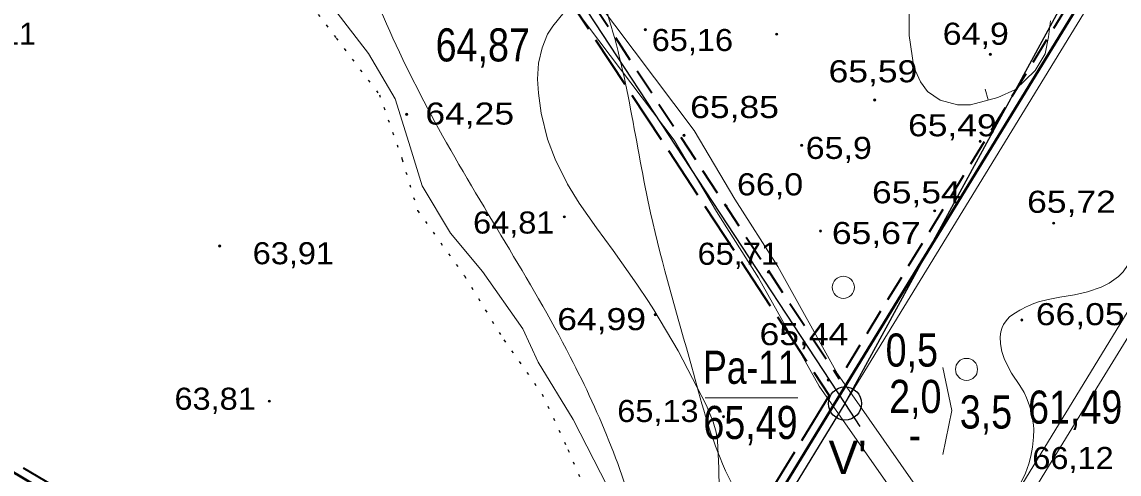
# Model space of a CAD drawing. Extents: x 628176 to 629009, y 6439913 to 6440496.
# Drawn here: x 628423 to 628522.3, y 6440112.2 to 6440153.1 of the extents above; entities that cross this region are included whole.
import ezdxf
from ezdxf.enums import TextEntityAlignment as Align

# ---------------------------------------------------------------- set-up
doc = ezdxf.new("R2010")
doc.units = 0
doc.header["$LTSCALE"] = 0.8
for name, pattern in [('DOTTED', [1.5, 0.3, -1.2]), ('LONG_DASHED', [7.5, 6, -1.5]), ('MEDIUM_DASHED', [4.5, 3, -1.5])]:
    doc.linetypes.add(name, pattern=pattern)
for name, color, linetype, lineweight in [('1', 7, 'Continuous', 13), ('11', 7, 'Continuous', 13), ('12', 7, 'Continuous', 13), ('14', 7, 'Continuous', 25), ('16', 7, 'Continuous', 13), ('21', 7, 'MEDIUM_DASHED', 35), ('3', 7, 'Continuous', 13), ('6', 7, 'Continuous', 13)]:
    doc.layers.add(name, color=color, linetype=linetype, lineweight=lineweight)

msp = doc.modelspace()

# ---------------------------------------------------------------- hatches: boundary and pattern name
at = {"layer": '1'}
for points in [[(628479.5318, 6440152.407, 1), (628479.3318, 6440152.407, 1)], [(628491.4248, 6440152.003, 1), (628491.2248, 6440152.003, 1)], [(628510.7677, 6440150.1687, 1), (628510.5677, 6440150.1687, 1)], [(628500.2824, 6440146.0325, 1), (628500.0824, 6440146.0325, 1)], [(628457.9211, 6440144.7306, 1), (628457.7211, 6440144.7306, 1)], [(628483.0399, 6440142.8434, 1), (628482.8399, 6440142.8434, 1)], [(628493.6894, 6440141.9411, 1), (628493.4894, 6440141.9411, 1)], [(628509.8395, 6440142.2948, 1), (628509.6395, 6440142.2948, 1)], [(628486.8417, 6440136.452, 1), (628486.6417, 6440136.452, 1)], [(628505.7258, 6440136.0029, 1), (628505.5258, 6440136.0029, 1)], [(628472.2044, 6440135.452, 1), (628472.0044, 6440135.452, 1)], [(628516.4912, 6440134.8783, 1), (628516.2912, 6440134.8783, 1)], [(628495.3881, 6440134.1627, 1), (628495.1881, 6440134.1627, 1)], [(628440.9944, 6440132.812, 1), (628440.7944, 6440132.812, 1)], [(628490.6579, 6440130.4443, 1), (628490.4579, 6440130.4443, 1)], [(628480.4462, 6440126.5862, 1), (628480.2462, 6440126.5862, 1)], [(628513.611, 6440126.118, 1), (628513.411, 6440126.118, 1)], [(628496.0967, 6440120.6667, 1), (628495.8967, 6440120.6667, 1)], [(628445.4907, 6440118.7561, 1), (628445.2907, 6440118.7561, 1)], [(628486.6119, 6440117.363, 1), (628486.4119, 6440117.363, 1)]]:
    msp.add_hatch(color=256, dxfattribs=at).paths.add_polyline_path(points)

# ---------------------------------------------------------------- linework, layer by layer
for p, q in [((628473.05, 6440157.63), (628483.84, 6440143.29)), ((628471.36, 6440156.57), (628482.04, 6440142.4)), ((628483.84, 6440143.29), (628487.53, 6440137.07)), ((628482.04, 6440142.4), (628485.88, 6440135.95)), ((628487.53, 6440137.07), (628491.42, 6440130.95)), ((628485.88, 6440135.95), (628489.69, 6440129.94)), ((628528.77, 6440133.79), (628516.03, 6440113)), ((628491.42, 6440130.95), (628496.83, 6440121.22)), ((628489.69, 6440129.94), (628495.17, 6440120.11)), ((628496.83, 6440121.22), (628503.9, 6440111.11)), ((628495.17, 6440120.11), (628502.32, 6440109.88)), ((628516.03, 6440113), (628509.39, 6440102.16))]:
    msp.add_line(p, q, dxfattribs=at)
at = {"layer": '1', "linetype": 'DOTTED', "lineweight": 25}
msp.add_lwpolyline([(628352.66, 6440194.21), (628361.18, 6440196.45), (628372.08, 6440198.4), (628381.65, 6440198.63), (628389.03, 6440197.45), (628395.92, 6440195.41), (628401.35, 6440193.56), (628413.35, 6440188.21), (628419.46, 6440183.8), (628429.96, 6440178.83), (628439.17, 6440172.52), (628442.41, 6440166.94), (628444.75, 6440162.25), (628447.66, 6440156.67), (628451.45, 6440151.65), (628455.36, 6440146.51), (628457.42, 6440140.66), (628458.82, 6440136.02), (628463.06, 6440130.1), (628466.63, 6440124.3), (628470.09, 6440119.39), (628472.43, 6440114.37), (628474.33, 6440109.9)], dxfattribs=at)
at = {"layer": '1'}
for centre, radius in [((628479.4318, 6440152.407), 0.1), ((628491.3248, 6440152.003), 0.1), ((628510.6677, 6440150.1687), 0.1), ((628500.1824, 6440146.0325), 0.1), ((628457.8211, 6440144.7306), 0.1), ((628482.9399, 6440142.8434), 0.1), ((628493.5894, 6440141.9411), 0.1), ((628509.7395, 6440142.2948), 0.1), ((628486.7417, 6440136.452), 0.1), ((628505.6258, 6440136.0029), 0.1), ((628472.1044, 6440135.452), 0.1), ((628516.3912, 6440134.8783), 0.1), ((628495.2881, 6440134.1627), 0.1), ((628440.8944, 6440132.812), 0.1), ((628490.5579, 6440130.4443), 0.1), ((628497.3542, 6440129.0729), 1), ((628480.3462, 6440126.5862), 0.1), ((628513.511, 6440126.118), 0.1), ((628508.5041, 6440121.636), 1), ((628495.9967, 6440120.6667), 0.1), ((628445.3907, 6440118.7561), 0.1), ((628486.5119, 6440117.363), 0.1)]:
    msp.add_circle(centre, radius, dxfattribs=at)
at = {"layer": '11'}
for points in [[(628497.5, 6440118.54), (628474.19, 6440080.39), (628272.25, 6440200.89), (628236.02, 6440221.83), (628393.19, 6440398.39)], [(628547.63, 6440210.77), (628520.9, 6440156.84), (628497.5, 6440118.54)], [(628320.67, 6440172), (628398.18, 6440198.42), (628472.21, 6440157.1), (628497.5, 6440118.54)]]:
    msp.add_lwpolyline(points, dxfattribs=at)
at = {"layer": '12'}
msp.add_line((628484.85, 6440119.07), (628493.25, 6440119.07), dxfattribs=at)
msp.add_lwpolyline([(628506.37, 6440121.82), (628507.18, 6440117.9), (628506.37, 6440113.92)], dxfattribs=at)
at = {"layer": '12', "lineweight": 25}
msp.add_circle((628497.5029, 6440118.5431), 1.5, dxfattribs=at)
at = {"layer": '14'}
for points in [[(628648.46, 6440349.59), (628617.39, 6440307.28), (628547.63, 6440210.77), (628497.5, 6440118.54), (628474.19, 6440080.39)], [(628326.62, 6440323.6), (628400.29, 6440209.22), (628472.21, 6440157.1), (628497.5, 6440118.54), (628498.85, 6440116.47)]]:
    msp.add_lwpolyline(points, dxfattribs=at)
at = {"layer": '16'}
for points in [[(628409.9, 6440254.58), (628412.29, 6440252.6), (628420.3, 6440245.33), (628427.75, 6440237.7), (628436.13, 6440222.98), (628444.52, 6440204.92), (628447.68, 6440184.24), (628451.78, 6440164.12), (628460.72, 6440143.45), (628472.64, 6440122.77), (628478.97, 6440106.2), (628480.84, 6440088.32)], [(628435.66, 6440253.61), (628435.76, 6440253.53), (628440.6, 6440249.8), (628446.19, 6440242.17), (628451.59, 6440233.41), (628456.06, 6440220.19), (628460.16, 6440203.24), (628465, 6440185.73), (628472.27, 6440163.38), (628475.81, 6440154.44), (628479.91, 6440135.81), (628483.63, 6440121.84), (628486.42, 6440113.09), (628492.01, 6440103.59)]]:
    msp.add_spline(points, degree=3, dxfattribs=at)
at = {"layer": '21'}
for points in [[(628546.49, 6440212.09), (628519.5, 6440157.62), (628496.99, 6440120.78)], [(628321.72, 6440173.24), (628398.26, 6440199.29), (628472.77, 6440157.71), (628496.99, 6440120.78)]]:
    msp.add_lwpolyline(points, dxfattribs=at)
at = {"layer": '21', "linetype": 'Continuous', "lineweight": 40}
for points in [[(628546.94, 6440211.19), (628520.2, 6440157.23), (628496.82, 6440118.96)], [(628496.82, 6440118.96), (628473.92, 6440081.48), (628320.39, 6440173.09)]]:
    msp.add_lwpolyline(points, dxfattribs=at)
at = {"layer": '21', "linetype": 'LONG_DASHED'}
for points in [[(628323.6, 6440172.11), (628398.09, 6440197.56), (628471.64, 6440156.5), (628496.07, 6440119.27)], [(628496.07, 6440119.27), (628473.65, 6440082.57), (628323.6, 6440172.11)]]:
    msp.add_lwpolyline(points, dxfattribs=at)
at = {"layer": '3'}
for p, q in [((628471.06, 6440152.71), (628472.09, 6440153.98)), ((628470.08, 6440150.75), (628469.77, 6440149.38)), ((628469.77, 6440149.38), (628469.68, 6440147.91)), ((628510.2, 6440147.03), (628510.46, 6440146.06)), ((628485.56, 6440116.88), (628484.96, 6440118.37)), ((628485.84, 6440115.95), (628485.56, 6440116.88)), ((628513.84, 6440112.23), (628514.16, 6440113.07))]:
    msp.add_line(p, q, dxfattribs=at)
for points in [[(628445.36, 6440164), (628448.12, 6440158.47), (628450.1, 6440155.43), (628451.32, 6440154.21), (628454.36, 6440150.26), (628456.79, 6440146.15), (628458.01, 6440142.2), (628459.23, 6440138.25), (628461.81, 6440133.99), (628464.7, 6440130.49), (628468.35, 6440125.32), (628469.72, 6440122.28), (628472.91, 6440117.11), (628476, 6440111.03)], [(628516.11, 6440153.21), (628515.92, 6440151.75), (628515.62, 6440150.23), (628514.71, 6440148.7), (628512.94, 6440147), (628511.35, 6440146.27), (628508.86, 6440145.6), (628507.7, 6440145.6), (628506.11, 6440146.02), (628504.96, 6440146.82), (628504.35, 6440147.67), (628503.74, 6440149.01), (628503.31, 6440151.87), (628503.31, 6440155.71)], [(628470.08, 6440150.75), (628470.59, 6440152), (628471.06, 6440152.71)], [(628484.96, 6440118.37), (628483.71, 6440120.82), (628482.39, 6440123.32), (628480.2, 6440127.04), (628479.71, 6440127.79), (628478.67, 6440129.35), (628476.52, 6440132.41), (628475.02, 6440134.47), (628473.45, 6440136.7), (628472.39, 6440138.41), (628471.26, 6440140.68), (628470.59, 6440142.48), (628470.01, 6440144.85), (628469.75, 6440146.65), (628469.68, 6440147.91)], [(628523.84, 6440133.6), (628523.68, 6440132.77), (628523.42, 6440131.91), (628523.08, 6440131.06), (628522.69, 6440130.46), (628522.27, 6440130.04), (628521.42, 6440129.44), (628520.68, 6440129.09), (628519.46, 6440128.65), (628518.27, 6440128.4), (628516.94, 6440128.17), (628515.9, 6440127.97), (628515.03, 6440127.75), (628514.61, 6440127.61)], [(628514.61, 6440127.61), (628514.13, 6440127.4), (628513.84, 6440127.27), (628513.52, 6440127.1), (628513.32, 6440126.99), (628512.94, 6440126.77), (628512.44, 6440126.42)], [(628512.44, 6440126.42), (628512.17, 6440126.16), (628511.85, 6440125.71), (628511.72, 6440125.43), (628511.6, 6440125.03)], [(628511.6, 6440125.03), (628511.54, 6440124.58), (628511.58, 6440123.96), (628511.7, 6440123.26), (628511.9, 6440122.63), (628512.29, 6440121.81), (628512.59, 6440121.31), (628513.34, 6440120.19), (628513.71, 6440119.54), (628513.93, 6440119.06), (628514.18, 6440118.43), (628514.32, 6440117.97), (628514.57, 6440116.62), (628514.59, 6440116.2), (628514.56, 6440115.5), (628514.48, 6440114.58), (628514.34, 6440113.79), (628514.16, 6440113.07)], [(628486.11, 6440110.8), (628486.09, 6440112.69), (628485.97, 6440115.2), (628485.84, 6440115.95)], [(628513.84, 6440112.23), (628513.44, 6440111.43), (628512.29, 6440109.51)]]:
    msp.add_lwpolyline(points, dxfattribs=at)
at = {"layer": '6'}
msp.add_lwpolyline([(628713.84, 6440420.66), (628737.18, 6440419.44), (628678.6, 6440359.86), (628654.6, 6440328.98), (628627.14, 6440290.88), (628627.14, 6440290.88), (628627.14, 6440290.88), (628562.66, 6440201.7), (628536.24, 6440148.38), (628489.22, 6440071.42), (628480.02, 6440052.78), (628457.03, 6440037.16), (628421.17, 6440028.67)], dxfattribs=at)

# ---------------------------------------------------------------- texts
at = {"layer": '1'}
msp.add_text('63,11', height=2, dxfattribs=at).set_placement((628417.55, 6440151.04))
for s, width, p in [('64,9', 1.15, (628506.35, 6440151.04)), ('65,16', 1.1, (628480.01, 6440150.47)), ('65,59', 1.2, (628496.02, 6440147.64)), ('64,25', 1.2, (628459.52, 6440143.81)), ('65,85', 1.2, (628483.49, 6440144.4)), ('65,49', 1.2, (628503.21, 6440142.75)), ('65,9', 1.15, (628493.95, 6440140.7)), ('66,0', 1.15, (628487.73, 6440137.4)), ('65,54', 1.2, (628499.95, 6440136.68)), ('65,72', 1.2, (628513.99, 6440135.82)), ('64,81', 1.1, (628463.84, 6440133.94)), ('65,67', 1.2, (628496.32, 6440132.99)), ('63,91', 1.1, (628443.89, 6440131.16)), ('65,71', 1.1, (628484.16, 6440131.11)), ('64,99', 1.2, (628471.46, 6440125.19)), ('66,05', 1.2, (628514.78, 6440125.64)), ('65,44', 1.2, (628489.77, 6440123.83)), ('63,81', 1.1, (628436.81, 6440117.98)), ('65,13', 1.1, (628476.89, 6440116.87)), ('66,12', 1.1, (628514.46, 6440112.61))]:
    msp.add_text(s, height=2, dxfattribs=dict(at, width=width)).set_placement(p)
at = {"layer": '11', "width": 0.85}
msp.add_text('0,5', height=3, dxfattribs=at).set_placement((628503.555, 6440121.89), align=Align.CENTER)
at = {"layer": '12'}
for s, width, p in [('64,87', 0.85, (628464.715, 6440149.53)), ('Pa-11', 0.8, (628488.95, 6440120.33)), ('2,0', 0.85, (628503.87, 6440117.69)), ('3,5', 0.85, (628510.265, 6440116.28)), ('61,49', 0.85, (628518.34, 6440116.72)), ('65,49', 0.85, (628488.95, 6440115.33)), ('-', 0.85, (628503.825, 6440114.23))]:
    msp.add_text(s, height=3, dxfattribs=dict(at, width=width)).set_placement(p, align=Align.CENTER)
at = {"layer": '14'}
msp.add_text("V'", height=3, dxfattribs=at).set_placement((628497.74, 6440112.17), align=Align.CENTER)

doc.saveas('drawing.dxf')
